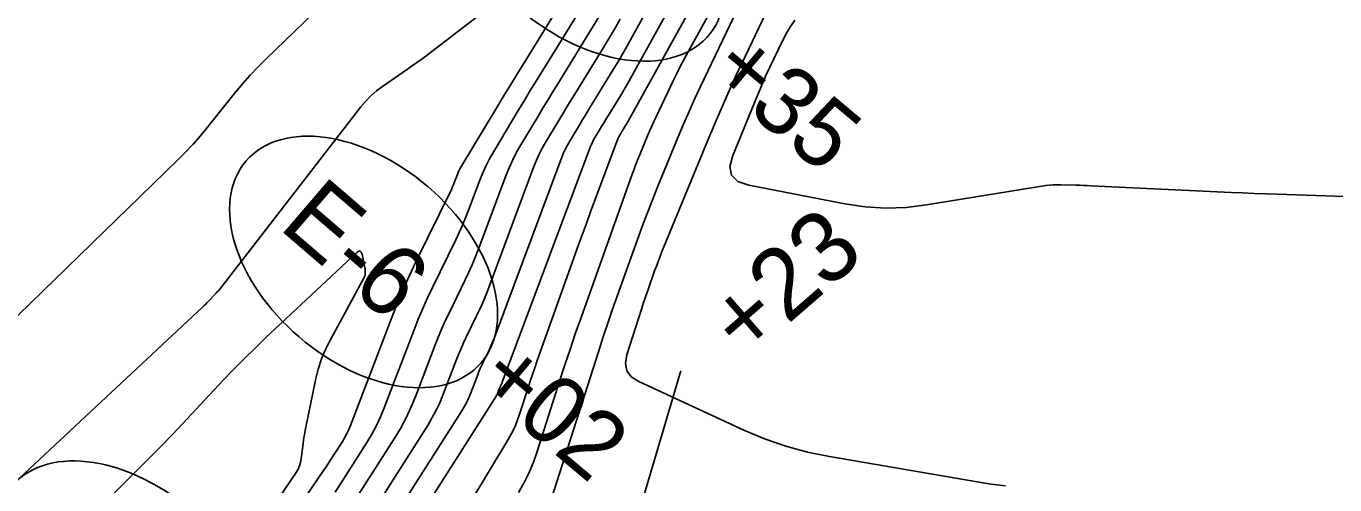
# Model space of a CAD drawing. Extents: x 1005228 to 1008882, y 1883389 to 1885754.
# Drawn here: x 1007830 to 1007945.8, y 1884530.4 to 1884571 of the extents above; entities that cross this region are included whole.
import ezdxf

# ---------------------------------------------------------------- set-up
doc = ezdxf.new("R2010")
doc.units = 0
for name, color, linetype in [('C-ANNO-NOTE', 7, 'Continuous'), ('R_Erosion', 7, 'Continuous'), ('S_BASELINE', 7, 'Continuous'), ('S_BRIDGE', 7, 'Continuous')]:
    doc.layers.add(name, color=color, linetype=linetype)

msp = doc.modelspace()

# ---------------------------------------------------------------- linework, layer by layer
at = {"layer": 'C-ANNO-NOTE'}
for points in [[(1007821.65, 1884538.05), (1007843.37, 1884559.15), (1007844.07, 1884559.85), (1007844.75, 1884560.57), (1007845.4, 1884561.31), (1007846.04, 1884562.08), (1007848.52, 1884565.17), (1007849.16, 1884565.93), (1007849.81, 1884566.68), (1007850.49, 1884567.4), (1007851.19, 1884568.1), (1007864.67, 1884581.14)], [(1007893.43, 1884580.99), (1007883.25, 1884562.62), (1007883.2, 1884562.52), (1007883.14, 1884562.42), (1007883.08, 1884562.32), (1007883.02, 1884562.22), (1007882.73, 1884561.74), (1007882.69, 1884561.69), (1007882.66, 1884561.63), (1007882.62, 1884561.57), (1007882.59, 1884561.52), (1007882.45, 1884561.29), (1007882.42, 1884561.23), (1007882.39, 1884561.17), (1007882.36, 1884561.11), (1007882.34, 1884561.05), (1007880.27, 1884555.54), (1007879.92, 1884554.6), (1007879.58, 1884553.66), (1007879.23, 1884552.71), (1007878.89, 1884551.77), (1007875.18, 1884541.37), (1007874.98, 1884540.79), (1007874.78, 1884540.2), (1007874.58, 1884539.62), (1007874.39, 1884539.04), (1007873.64, 1884536.69), (1007873.44, 1884536.11), (1007873.21, 1884535.55), (1007872.94, 1884535), (1007872.64, 1884534.47), (1007867.42, 1884525.79)], [(1007873.55, 1884529.77), (1007874.04, 1884530.64), (1007874.48, 1884531.54), (1007874.86, 1884532.46), (1007875.2, 1884533.4), (1007877.21, 1884539.7), (1007877.65, 1884541.07), (1007878.11, 1884542.43), (1007878.57, 1884543.79), (1007879.05, 1884545.15), (1007883.58, 1884557.84), (1007883.74, 1884558.28), (1007883.9, 1884558.72), (1007884.07, 1884559.15), (1007884.25, 1884559.58), (1007884.96, 1884561.31), (1007885.14, 1884561.74), (1007885.33, 1884562.16), (1007885.52, 1884562.59), (1007885.71, 1884563.01), (1007887.22, 1884566.17), (1007887.55, 1884566.84), (1007887.88, 1884567.5), (1007888.22, 1884568.15), (1007888.58, 1884568.8), (1007895.82, 1884581.89)], [(1007866.05, 1884529.61), (1007871.53, 1884538.23), (1007871.57, 1884538.3), (1007871.61, 1884538.37), (1007871.65, 1884538.44), (1007871.68, 1884538.52), (1007871.81, 1884538.87), (1007871.84, 1884538.93), (1007871.86, 1884538.98), (1007871.88, 1884539.04), (1007871.91, 1884539.09), (1007872.02, 1884539.31), (1007872.04, 1884539.36), (1007872.07, 1884539.42), (1007872.09, 1884539.47), (1007872.11, 1884539.53), (1007879.86, 1884560.23), (1007879.95, 1884560.46), (1007880.05, 1884560.68), (1007880.16, 1884560.89), (1007880.28, 1884561.1), (1007880.78, 1884561.93), (1007880.9, 1884562.13), (1007881.03, 1884562.34), (1007881.15, 1884562.54), (1007881.28, 1884562.75), (1007882.34, 1884564.48), (1007882.56, 1884564.84), (1007882.77, 1884565.2), (1007882.98, 1884565.56), (1007883.19, 1884565.92), (1007891.04, 1884580.09)], [(1007880.91, 1884578.94), (1007874.04, 1884567.78), (1007873.45, 1884566.83), (1007872.87, 1884565.87), (1007872.29, 1884564.92), (1007871.72, 1884563.97), (1007868.45, 1884558.54), (1007868.36, 1884558.39), (1007868.28, 1884558.23), (1007868.2, 1884558.07), (1007868.14, 1884557.9), (1007867.89, 1884557.24), (1007867.82, 1884557.07), (1007867.76, 1884556.91), (1007867.68, 1884556.74), (1007867.61, 1884556.58), (1007864.44, 1884550.11), (1007863.9, 1884548.97), (1007863.38, 1884547.82), (1007862.89, 1884546.66), (1007862.43, 1884545.48), (1007858.69, 1884535.7), (1007858.54, 1884535.34), (1007858.37, 1884534.99), (1007858.19, 1884534.65), (1007857.99, 1884534.31), (1007857.16, 1884533), (1007856.95, 1884532.68), (1007856.73, 1884532.35), (1007856.52, 1884532.03), (1007856.3, 1884531.71), (1007850.35, 1884522.95)], [(1007859.43, 1884522.69), (1007868.54, 1884536.99), (1007868.75, 1884537.34), (1007868.94, 1884537.7), (1007869.12, 1884538.07), (1007869.27, 1884538.45), (1007869.94, 1884540.19), (1007870.05, 1884540.47), (1007870.16, 1884540.75), (1007870.29, 1884541.02), (1007870.42, 1884541.29), (1007870.94, 1884542.37), (1007871.07, 1884542.65), (1007871.2, 1884542.92), (1007871.31, 1884543.2), (1007871.42, 1884543.48), (1007877.38, 1884559.42), (1007877.54, 1884559.8), (1007877.71, 1884560.18), (1007877.9, 1884560.55), (1007878.11, 1884560.91), (1007878.96, 1884562.33), (1007879.18, 1884562.69), (1007879.4, 1884563.05), (1007879.61, 1884563.4), (1007879.83, 1884563.76), (1007881.66, 1884566.74), (1007882.04, 1884567.35), (1007882.41, 1884567.97), (1007882.77, 1884568.6), (1007883.12, 1884569.23), (1007888.65, 1884579.2)], [(1007916.63, 1884530.36), (1007915.37, 1884530.52), (1007914.12, 1884530.72), (1007901.05, 1884532.95), (1007899.1, 1884533.35), (1007897.19, 1884533.87), (1007895.32, 1884534.52), (1007893.48, 1884535.29), (1007884.18, 1884539.58), (1007883.52, 1884540), (1007883.13, 1884540.53), (1007883, 1884541.19), (1007883.13, 1884541.95), (1007884.45, 1884546.08), (1007884.58, 1884546.49), (1007884.72, 1884546.91), (1007884.86, 1884547.32), (1007885.01, 1884547.73), (1007885.59, 1884549.37), (1007885.74, 1884549.78), (1007885.89, 1884550.18), (1007886.05, 1884550.59), (1007886.21, 1884550.99), (1007890.39, 1884561.13), (1007891.15, 1884562.95), (1007891.94, 1884564.76), (1007892.75, 1884566.55), (1007893.59, 1884568.34), (1007898.49, 1884578.63)], [(1007828.03, 1884529.77), (1007845.59, 1884546.16), (1007845.71, 1884546.28), (1007845.84, 1884546.4), (1007845.96, 1884546.53), (1007846.08, 1884546.65), (1007846.73, 1884547.35), (1007846.76, 1884547.38), (1007846.8, 1884547.41), (1007846.83, 1884547.45), (1007846.86, 1884547.48), (1007847, 1884547.61), (1007847.04, 1884547.64), (1007847.07, 1884547.67), (1007847.1, 1884547.71), (1007847.13, 1884547.75), (1007859.6, 1884563.88), (1007860.03, 1884564.39), (1007860.49, 1884564.86), (1007860.99, 1884565.29), (1007861.52, 1884565.69), (1007863.72, 1884567.21), (1007864.27, 1884567.59), (1007864.81, 1884567.98), (1007865.35, 1884568.37), (1007865.88, 1884568.78), (1007878.42, 1884578.42)], [(1007880.85, 1884575.49), (1007875.48, 1884566.77), (1007874.99, 1884565.97), (1007874.5, 1884565.17), (1007874.01, 1884564.36), (1007873.53, 1884563.56), (1007871.35, 1884559.94), (1007871, 1884559.33), (1007870.68, 1884558.7), (1007870.38, 1884558.05), (1007870.12, 1884557.4), (1007869.12, 1884554.74), (1007868.87, 1884554.07), (1007868.59, 1884553.42), (1007868.31, 1884552.77), (1007868, 1884552.13), (1007865.93, 1884547.9), (1007865.49, 1884546.98), (1007865.08, 1884546.05), (1007864.68, 1884545.11), (1007864.31, 1884544.16), (1007861.67, 1884537.27), (1007861.34, 1884536.47), (1007860.97, 1884535.69), (1007860.57, 1884534.93), (1007860.12, 1884534.19), (1007858.26, 1884531.27), (1007857.79, 1884530.54), (1007857.32, 1884529.81)], [(1007859.04, 1884529.02), (1007862.55, 1884534.53), (1007863.1, 1884535.44), (1007863.6, 1884536.38), (1007864.05, 1884537.34), (1007864.46, 1884538.32), (1007866.18, 1884542.84), (1007866.47, 1884543.56), (1007866.77, 1884544.28), (1007867.09, 1884545), (1007867.43, 1884545.7), (1007868.8, 1884548.51), (1007869.13, 1884549.21), (1007869.45, 1884549.92), (1007869.75, 1884550.64), (1007870.03, 1884551.37), (1007872.43, 1884557.78), (1007872.72, 1884558.49), (1007873.03, 1884559.19), (1007873.38, 1884559.86), (1007873.76, 1884560.53), (1007875.34, 1884563.15), (1007875.74, 1884563.81), (1007876.13, 1884564.46), (1007876.53, 1884565.11), (1007876.93, 1884565.77), (1007880.72, 1884571.92)], [(1007946.64, 1884555.95), (1007940.67, 1884556.15), (1007939.64, 1884556.18), (1007938.62, 1884556.22), (1007937.6, 1884556.27), (1007936.58, 1884556.31), (1007924.19, 1884556.89), (1007923.86, 1884556.91), (1007923.52, 1884556.92), (1007923.19, 1884556.94), (1007922.85, 1884556.95), (1007921.52, 1884556.99), (1007921.18, 1884556.99), (1007920.85, 1884556.98), (1007920.52, 1884556.95), (1007920.19, 1884556.91), (1007909.64, 1884555.2), (1007907.83, 1884554.99), (1007906.02, 1884554.93), (1007904.21, 1884555.04), (1007902.41, 1884555.31), (1007893.91, 1884556.96), (1007892.96, 1884557.29), (1007892.4, 1884557.84), (1007892.25, 1884558.6), (1007892.5, 1884559.58), (1007894.65, 1884564.82), (1007894.92, 1884565.45), (1007895.19, 1884566.08), (1007895.47, 1884566.7), (1007895.76, 1884567.32), (1007896.94, 1884569.79), (1007897.25, 1884570.4), (1007897.6, 1884570.98), (1007897.98, 1884571.55)], [(1007847.27, 1884521.82), (1007853.87, 1884531.54), (1007854.04, 1884531.82), (1007854.17, 1884532.12), (1007854.27, 1884532.43), (1007854.33, 1884532.76), (1007854.48, 1884534.09), (1007854.53, 1884534.42), (1007854.58, 1884534.75), (1007854.63, 1884535.08), (1007854.7, 1884535.41), (1007855.63, 1884539.84), (1007855.83, 1884540.68), (1007856.1, 1884541.49), (1007856.42, 1884542.29), (1007856.8, 1884543.06), (1007859.91, 1884548.83), (1007859.93, 1884548.88), (1007859.95, 1884548.94), (1007859.97, 1884548.99), (1007859.97, 1884549.05), (1007859.98, 1884549.29), (1007859.98, 1884549.35), (1007859.98, 1884549.41), (1007859.97, 1884549.46), (1007859.97, 1884549.52), (1007859.7, 1884550.84), (1007859.64, 1884551.03), (1007859.54, 1884551.12), (1007859.41, 1884551.11), (1007859.25, 1884550.99), (1007851.17, 1884543.44), (1007850.22, 1884542.52), (1007849.27, 1884541.6), (1007848.34, 1884540.65), (1007847.43, 1884539.7), (1007843.81, 1884535.84), (1007842.9, 1884534.87), (1007841.98, 1884533.92), (1007841.05, 1884532.98), (1007840.11, 1884532.04), (1007835.26, 1884527.23)]]:
    msp.add_lwpolyline(points, dxfattribs=at)
at = {"layer": 'R_Erosion'}
msp.add_lwpolyline([(1007887.92, 1884540.52), (1007883.68, 1884526.3), (1007909.55, 1884514.42), (1007962.35, 1884508.01), (1007992.33, 1884515.45)], dxfattribs=at)
for centre, major_axis in [((1007879.73, 1884578.83), (10.77, -8.47)), ((1007859.84, 1884550.16), (10.39, -8.93)), ((1007839.1, 1884521.38), (10.28, -9.05))]:
    msp.add_ellipse(centre, major_axis=major_axis, ratio=0.638788, dxfattribs=at)
at = {"layer": 'S_BRIDGE'}
for points in [[(1007894.57, 1884576), (1007889.65, 1884565.68), (1007889.13, 1884564.57), (1007888.63, 1884563.46), (1007888.14, 1884562.34), (1007887.67, 1884561.22), (1007885.82, 1884556.71), (1007885.36, 1884555.58), (1007884.92, 1884554.44), (1007884.49, 1884553.3), (1007884.07, 1884552.16), (1007882.27, 1884547.12), (1007881.84, 1884545.9), (1007881.42, 1884544.67), (1007881.01, 1884543.44), (1007880.61, 1884542.2), (1007875.97, 1884527.67)], [(1007859.23, 1884525.86), (1007865.54, 1884535.76), (1007865.92, 1884536.39), (1007866.27, 1884537.04), (1007866.58, 1884537.71), (1007866.86, 1884538.39), (1007868.06, 1884541.52), (1007868.26, 1884542.02), (1007868.47, 1884542.52), (1007868.69, 1884543.01), (1007868.92, 1884543.5), (1007869.87, 1884545.44), (1007870.1, 1884545.93), (1007870.32, 1884546.42), (1007870.53, 1884546.92), (1007870.73, 1884547.42), (1007874.91, 1884558.6), (1007875.13, 1884559.15), (1007875.37, 1884559.68), (1007875.64, 1884560.21), (1007875.93, 1884560.72), (1007877.15, 1884562.74), (1007877.46, 1884563.25), (1007877.76, 1884563.75), (1007878.07, 1884564.26), (1007878.38, 1884564.76), (1007880.99, 1884568.99), (1007881.52, 1884569.87), (1007882.04, 1884570.75), (1007882.55, 1884571.64)]]:
    msp.add_lwpolyline(points, dxfattribs=at)

# ---------------------------------------------------------------- texts
at = {"layer": 'R_Erosion'}
msp.add_text('E-6', height=6.25, rotation=319.3363, dxfattribs=at).set_placement((1007852.22, 1884553.19))
at = {"layer": 'S_BASELINE'}
for s, height, rotation, p in [('+35', 6, 320, (1007890.09, 1884566.55)), ('+23', 6.25, 41.0393, (1007893.65, 1884541.37)), ('+02', 6, 320, (1007869.51, 1884539.22))]:
    msp.add_text(s, height=height, rotation=rotation, dxfattribs=at).set_placement(p)

doc.saveas('drawing.dxf')
